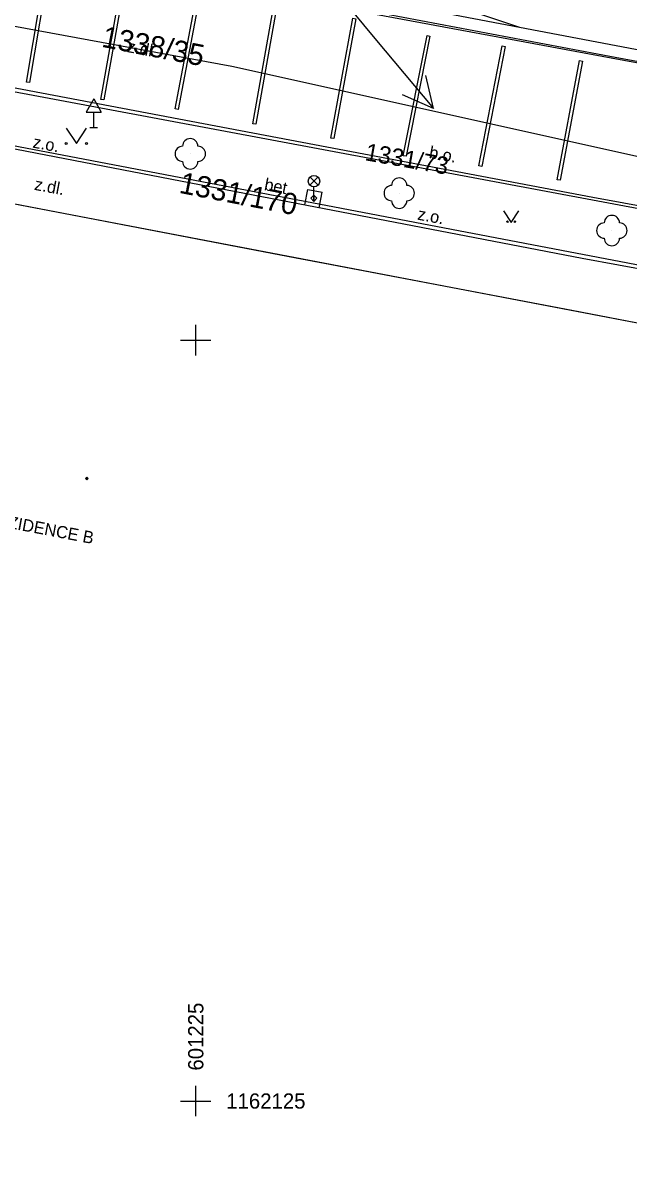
# Model space of a CAD drawing. Extents: x -601602 to -600882, y -1162594 to -1161950.
# Drawn here: x -601230.67 to -601210.78, y -1162127.4 to -1162089.58 of the extents above; entities that cross this region are included whole.
import ezdxf

# ---------------------------------------------------------------- set-up
doc = ezdxf.new("R2010")
doc.units = 0
for name, color, linetype in [('KN_Hranice parcel', 7, 'Continuous'), ('KN_Parcelní čísla', 7, 'Continuous'), ('KN_Pop  PČ popisy', 7, 'Continuous'), ('KN_Značky kultur', 7, 'Continuous'), ('Vrstva 14', 7, 'Continuous'), ('Vrstva 15', 7, 'Continuous'), ('Vrstva 19', 7, 'Continuous'), ('Vrstva 29', 7, 'Continuous'), ('Vrstva 4', 7, 'Continuous'), ('Vrstva 49', 7, 'Continuous'), ('VRSTVA 5', 7, 'Continuous'), ('Vrstva 7', 7, 'Continuous'), ('X_SOUR_KRIZKY_SEVER', 7, 'Continuous')]:
    doc.layers.add(name, color=color, linetype=linetype)

# ---------------------------------------------------------------- blocks, each defined once
blk = doc.blocks.new('1029_51')
at = {"layer": 'KN_Pop  PČ popisy'}
for p, q in [((0, 0), (1.929, -2.299)), ((1.929, -2.299), (1.669, -1.21)), ((1.929, -2.299), (0.902, -1.854))]:
    blk.add_line(p, q, dxfattribs=at)

msp = doc.modelspace()

# ---------------------------------------------------------------- linework, layer by layer
at = {"layer": 'KN_Hranice parcel'}
for p, q in [((-601222.67, -1162086.92), (-601214.37, -1162089.72)), ((-601222.99, -1162088.07), (-601214.37, -1162089.72)), ((-601247.89, -1162088.66), (-601202.36, -1162097.2)), ((-601214.37, -1162089.72), (-601180.06, -1162096.24))]:
    msp.add_line(p, q, dxfattribs=at)
for points in [[(-601202.1, -1162095.83), (-601201.76, -1162093.97), (-601201.49, -1162092.55), (-601211.36, -1162090.74), (-601223.12, -1162088.55), (-601230.57, -1162087.16), (-601239.11, -1162085.56), (-601244.03, -1162084.64), (-601247.06, -1162084.07)], [(-601247.52, -1162086.62), (-601244.9, -1162087.11), (-601239.93, -1162088.03), (-601233.95, -1162089.13), (-601231.85, -1162089.52), (-601223.82, -1162091), (-601202.1, -1162095.83)], [(-601202.36, -1162097.2), (-601202.56, -1162098.21), (-601202.97, -1162098.77), (-601203.59, -1162098.85), (-601247.45, -1162090.47), (-601247.92, -1162090.19), (-601248.07, -1162089.68), (-601247.89, -1162088.66)], [(-601200.05, -1162101.62), (-601200.02, -1162101.45), (-601257.65, -1162090.43), (-601258.35, -1162094.11), (-601259.98, -1162093.8), (-601271.27, -1162152.93), (-601269.66, -1162153.24), (-601270.36, -1162156.92), (-601270.25, -1162156.94)]]:
    msp.add_lwpolyline(points, dxfattribs=at)
at = {"layer": 'KN_Pop  PČ popisy'}
msp.add_line((-601220.85, -1162087.99), (-601219.12, -1162090.09), dxfattribs=at)
at = {"layer": 'KN_Značky kultur'}
for p, q in [((-601229.255, -1162093.037), (-601228.92, -1162093.54)), ((-601228.92, -1162093.54), (-601228.585, -1162093.037))]:
    msp.add_line(p, q, dxfattribs=at)
for centre in [(-601229.255, -1162093.54), (-601228.585, -1162093.54)]:
    msp.add_circle(centre, 0.0335, dxfattribs=at)
at = {"layer": 'Vrstva 14'}
for p, q in [((-601214.896, -1162095.757), (-601214.646, -1162096.131)), ((-601214.646, -1162096.131), (-601214.396, -1162095.757))]:
    msp.add_line(p, q, dxfattribs=at)
for points in [[(-601214.771, -1162096.132), (-601214.796, -1162096.107), (-601214.771, -1162096.082)], [(-601214.771, -1162096.132), (-601214.771, -1162096.082), (-601214.746, -1162096.107)], [(-601214.521, -1162096.132), (-601214.546, -1162096.107), (-601214.521, -1162096.082)], [(-601214.521, -1162096.132), (-601214.521, -1162096.082), (-601214.496, -1162096.107)]]:
    msp.add_lwpolyline(points, close=True, dxfattribs=at)
for centre in [(-601225.18, -1162093.88), (-601218.32, -1162095.17), (-601211.34, -1162096.4)]:
    msp.add_circle(centre, 0.00025, dxfattribs=at)
for centre, start, end in [((-601225.18, -1162093.63), 0, 180), ((-601225.43, -1162093.88), 90, 270), ((-601224.93, -1162093.88), 270, 90), ((-601225.18, -1162094.13), 180, 360), ((-601218.57, -1162095.17), 90, 270), ((-601218.32, -1162094.92), 0, 180), ((-601218.07, -1162095.17), 270, 90), ((-601218.32, -1162095.42), 180, 360), ((-601211.59, -1162096.4), 90, 270), ((-601211.34, -1162096.15), 0, 180), ((-601211.09, -1162096.4), 270, 90), ((-601211.34, -1162096.65), 180, 360)]:
    msp.add_arc(centre, 0.25, start, end, dxfattribs=at)
at = {"layer": 'Vrstva 15'}
for points in [[(-601228.579, -1162104.593), (-601228.623, -1162104.549), (-601228.579, -1162104.505)], [(-601228.579, -1162104.593), (-601228.579, -1162104.505), (-601228.536, -1162104.549)]]:
    msp.add_lwpolyline(points, close=True, dxfattribs=at)
at = {"layer": 'Vrstva 19'}
for p, q in [((-601228.35, -1162092.077), (-601228.6, -1162092.51)), ((-601228.35, -1162092.077), (-601228.1, -1162092.51)), ((-601228.6, -1162092.51), (-601228.1, -1162092.51)), ((-601228.35, -1162093.01), (-601228.35, -1162092.51)), ((-601228.475, -1162093.01), (-601228.225, -1162093.01))]:
    msp.add_line(p, q, dxfattribs=at)
at = {"layer": 'Vrstva 29'}
for p, q in [((-601221.252, -1162094.909), (-601220.988, -1162094.645)), ((-601220.984, -1162094.908), (-601221.248, -1162094.643)), ((-601221.12, -1162095.24), (-601221.12, -1162094.965))]:
    msp.add_line(p, q, dxfattribs=at)
for points in [[(-601221.12, -1162095.44), (-601221.22, -1162095.34), (-601221.12, -1162095.24)], [(-601221.12, -1162095.44), (-601221.12, -1162095.24), (-601221.02, -1162095.34)]]:
    msp.add_lwpolyline(points, close=True, dxfattribs=at)
msp.add_circle((-601221.12, -1162094.778), 0.188, dxfattribs=at)
at = {"layer": 'Vrstva 4'}
msp.add_line((-601221.7, -1162097.302), (-601232.055, -1162095.322), dxfattribs=at)
at = {"layer": 'VRSTVA 5'}
msp.add_line((-601220.77, -1162097.48), (-601221.7, -1162097.302), dxfattribs=at)
at = {"layer": 'Vrstva 7'}
for p, q in [((-601211.23, -1162090.71), (-601224.25, -1162088.25)), ((-601224.75, -1162092.89), (-601237.01, -1162090.58)), ((-601201.39, -1162092.56), (-601211.23, -1162090.71)), ((-601237.49, -1162092.44), (-601224.88, -1162094.89)), ((-601211.96, -1162095.31), (-601224.75, -1162092.89)), ((-601224.88, -1162094.89), (-601212.32, -1162097.31)), ((-601221.418, -1162095.557), (-601221.32, -1162095.05)), ((-601221.32, -1162095.05), (-601220.85, -1162095.14)), ((-601220.948, -1162095.648), (-601220.85, -1162095.14)), ((-601202.21, -1162097.11), (-601211.96, -1162095.31)), ((-601212.32, -1162097.31), (-601203.54, -1162098.92)), ((-601212.66, -1162099.03), (-601220.77, -1162097.48)), ((-601205.262, -1162100.442), (-601212.66, -1162099.03))]:
    msp.add_line(p, q, dxfattribs=at)
for points in [[(-601229.791, -1162087.558), (-601230.461, -1162091.538), (-601230.559, -1162091.522), (-601229.889, -1162087.542)], [(-601227.321, -1162088.159), (-601228.021, -1162092.109), (-601228.119, -1162092.091), (-601227.419, -1162088.141)], [(-601224.831, -1162088.489), (-601225.581, -1162092.419), (-601225.679, -1162092.401), (-601224.929, -1162088.471)], [(-601222.331, -1162088.959), (-601223.031, -1162092.909), (-601223.129, -1162092.891), (-601222.429, -1162088.941)], [(-601219.741, -1162089.439), (-601220.471, -1162093.379), (-601220.569, -1162093.361), (-601219.839, -1162089.421)], [(-601217.311, -1162090.01), (-601218.091, -1162093.96), (-601218.189, -1162093.94), (-601217.409, -1162089.99)], [(-601214.841, -1162090.35), (-601215.611, -1162094.29), (-601215.709, -1162094.27), (-601214.939, -1162090.33)], [(-601212.301, -1162090.829), (-601213.041, -1162094.749), (-601213.139, -1162094.731), (-601212.399, -1162090.811)]]:
    msp.add_lwpolyline(points, close=True, dxfattribs=at)
at = {"layer": 'X_SOUR_KRIZKY_SEVER'}
for p, q in [((-601225, -1162100.5), (-601225, -1162099.5)), ((-601225.5, -1162100), (-601224.5, -1162100)), ((-601225, -1162125.5), (-601225, -1162124.5)), ((-601225.5, -1162125), (-601224.5, -1162125))]:
    msp.add_line(p, q, dxfattribs=at)

# ---------------------------------------------------------------- block references
at = {"layer": 'KN_Pop  PČ popisy'}
msp.add_blockref('1029_51', (-601219.12, -1162090.09), dxfattribs=at)

# ---------------------------------------------------------------- texts
at = {"layer": 'KN_Parcelní čísla'}
for s, height, rotation, p in [('1338/35', 0.7, 349, (-601228.117, -1162090.358)), ('1331/73', 0.5695, 350, (-601219.469, -1162094.087)), ('1331/170', 0.7, 349, (-601225.573, -1162095.157))]:
    msp.add_text(s, height=height, rotation=rotation, dxfattribs=at).set_placement(p)
at = {"layer": 'Vrstva 49'}
for s, rotation, p in [('z.o.', 349.4716, (-601230.372, -1162093.672)), ('b.o.', 349.4716, (-601217.363, -1162094.011)), ('bet.', 349.2301, (-601222.773, -1162095.067)), ('z.dl.', 349.2301, (-601230.319, -1162095.059)), ('z.o.', 349.4716, (-601217.742, -1162096.039)), ('budova REZIDENCE B', 349.2315, (-601233.791, -1162105.672))]:
    msp.add_text(s, height=0.4, rotation=rotation, dxfattribs=at).set_placement(p)
at = {"layer": 'Vrstva 7'}
msp.add_text('z.dl.', height=0.4, rotation=349.2301, dxfattribs=at).set_placement((-601227.274, -1162090.531))
at = {"layer": 'X_SOUR_KRIZKY_SEVER'}
msp.add_text('601225', height=0.5, rotation=90, dxfattribs=at).set_placement((-601224.75, -1162124))
msp.add_text('1162125', height=0.5, dxfattribs=at).set_placement((-601224, -1162125.25))

doc.saveas('drawing.dxf')
